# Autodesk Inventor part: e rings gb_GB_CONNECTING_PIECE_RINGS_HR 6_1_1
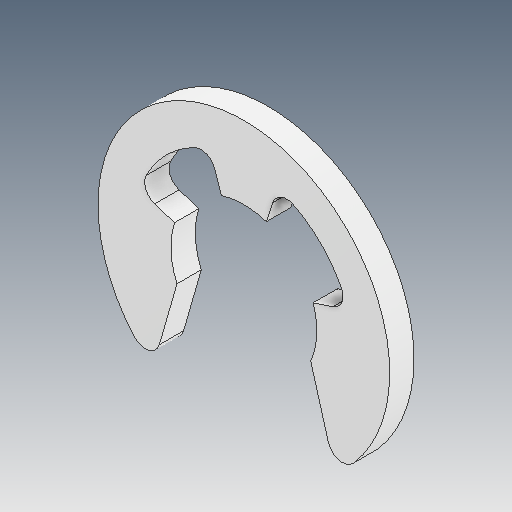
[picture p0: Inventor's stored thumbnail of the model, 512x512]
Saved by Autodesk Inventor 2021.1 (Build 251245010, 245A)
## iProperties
Created: 2021-05
Part Number: e rings gb_GB_CONNECTING_PIECE_RINGS_HR 6_1_1
Material: Ogólny
Document SubType Name: Modeling
Designer: user
Density: 1 g/cm^3
Appearance: Domyślna
Author: user
Revision Number: ÈÎºÎ
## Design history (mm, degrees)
feature "ÊäÈë1"
node "Bryła1"
